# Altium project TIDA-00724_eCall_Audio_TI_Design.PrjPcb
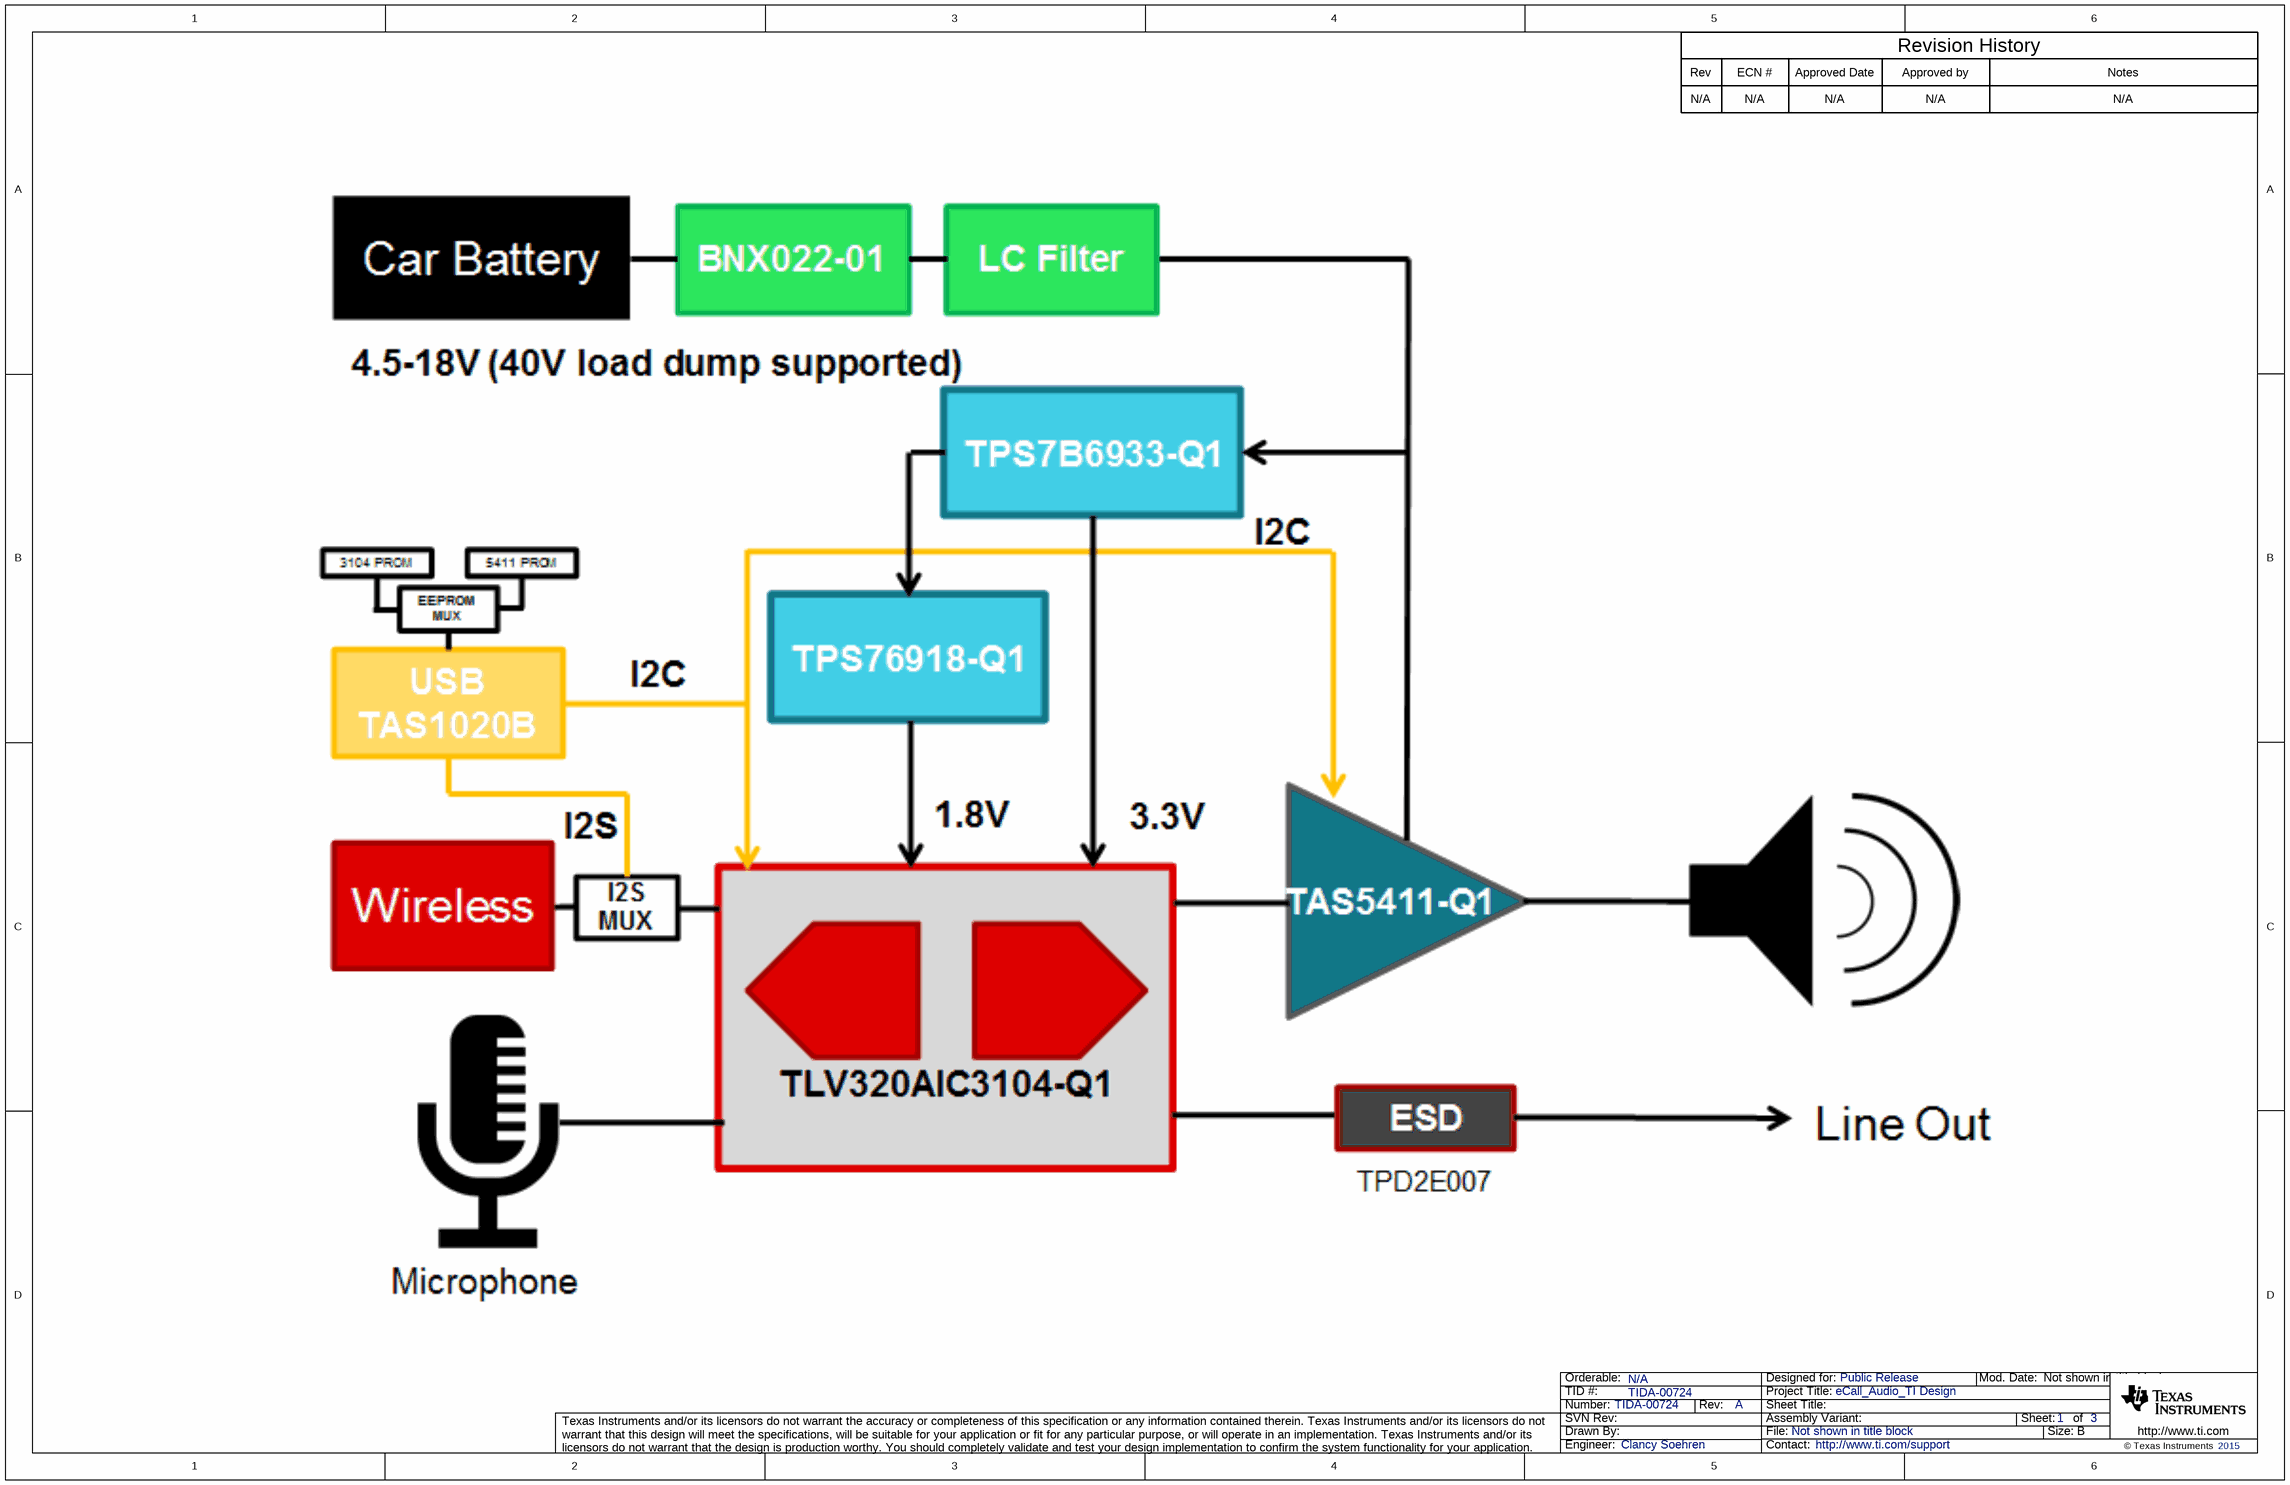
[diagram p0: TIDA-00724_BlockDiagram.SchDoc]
CopyrightYear: 2015; EVM_Orderable: N/A; PCB_Layout: Krypton Solutions; PCB_Rev: A; PRJ_Customer: Public Release; PRJ_Engineer: Clancy Soehren; PRJ_Number: TIDA-00724; PRJ_Title: eCall_Audio_TI Design; SCH_Rev: A; TechSupport: http://www.ti.com/support; TID: TIDA-00724
5 sheets, 148 parts. Net scope: global (net labels, ports and power ports of the same name join across sheets).
Board file: TIDA-00724_BRD.PcbDoc
Sheets:
  TIDA-00724_BlockDiagram.SchDoc
  TIDA-00724_Hardware.SchDoc
  TIDA-00724_Power.SchDoc
  TIDA-00724_TAS1020.SchDoc
  TIDA-00724_Audio.SchDoc

## Sheet TIDA-00724_BlockDiagram.SchDoc
size 431 x 279 mm; Date: Not shown in title block; ApprovedBy: Not shown in title block; CheckedBy: Not shown in title block; Author: Not shown in title block; CompanyName: Not shown in title block; Engineer: Not shown in title block; Organization: Not shown in title block; Address1: Not shown in title block; Address2: Not shown in title block; Address3: Not shown in title block; Address4: Not shown in title block; DocumentNumber: 1; Revision: Use project parameter SCH_Rev; SheetNumber: 1; SheetTotal: 3; PageSetup: Record=PageOptions¦CenterHorizontal=True¦CenterVertical=True¦PrintScale=1.00¦XCorrection=1.00¦YCorrection=1.00¦PrintKind=0¦BorderSize=5000000¦LeftOffset=0¦BottomOffset=0¦Orientation=2¦PaperLength=1000¦PaperWidth=1000¦Scale=100¦PaperSource=15¦PrintQuality=600¦MediaType=1¦DitherType=10¦PaperKind=Letter¦PrintScaleMode=1

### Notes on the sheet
- Rev
- N/A
- ECN #
- Approved Date
- Approved by
- Revision History
- Notes

## Sheet TIDA-00724_Hardware.SchDoc
size 431 x 279 mm; Date: Not shown in title block; ApprovedBy: Not shown in title block; CheckedBy: Not shown in title block; Author: Not shown in title block; CompanyName: Not shown in title block; Engineer: Not shown in title block; Organization: Not shown in title block; Address1: Not shown in title block; Address2: Not shown in title block; Address3: Not shown in title block; Address4: Not shown in title block; DocumentNumber: 1; Revision: Use project parameter SCH_Rev; SheetNumber: 3; SheetTotal: 3; PageSetup: Record=PageOptions¦CenterHorizontal=True¦CenterVertical=True¦PrintScale=1.00¦XCorrection=1.00¦YCorrection=1.00¦PrintKind=0¦BorderSize=5000000¦LeftOffset=0¦BottomOffset=0¦Orientation=2¦PaperLength=1000¦PaperWidth=1000¦Scale=100¦PaperSource=15¦PrintQuality=600¦MediaType=1¦DitherType=10¦PaperKind=Letter¦PrintScaleMode=1
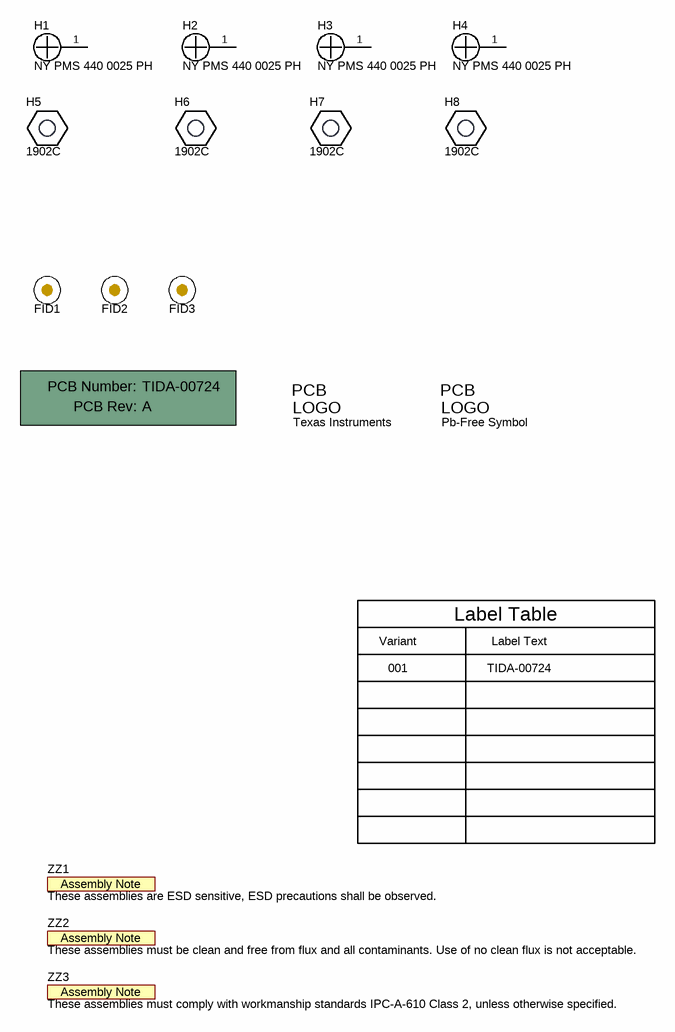
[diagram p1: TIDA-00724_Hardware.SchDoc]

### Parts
!PCB1  Printed Circuit Board  (value not drawn)  (mechanical)
FID1  Fiducial  [Fiducial10-20]  (value not drawn)
FID2  Fiducial  [Fiducial10-20]  (value not drawn)
FID3  Fiducial  [Fiducial10-20]  (value not drawn)
H1  NY PMS 440 0025 PH  [NY PMS 440 0025 PH]
H2  NY PMS 440 0025 PH  [NY PMS 440 0025 PH]
H3  NY PMS 440 0025 PH  [NY PMS 440 0025 PH]
H4  NY PMS 440 0025 PH  [NY PMS 440 0025 PH]
H5  1902C  [Keystone_1902C]
H6  1902C  [Keystone_1902C]
H7  1902C  [Keystone_1902C]
H8  1902C  [Keystone_1902C]
Logo1  Texas Instruments  [TI_Stacked_Overlay_Small]  (no BOM)
Logo2  Pb-Free Symbol  [Pb-Free_Overlay_Small]  (no BOM)
ZZ1  These assemblies are ESD sensitive, ESD precautions shall be observed.  [AssemblyNote]  (no BOM)
ZZ2  These assemblies must be clean and free from flux and all contaminants. Use of no clean flux is not acceptable.  [AssemblyNote]  (no BOM)
ZZ3  These assemblies must comply with workmanship standards IPC-A-610 Class 2, unless otherwise specified.  [AssemblyNote]  (no BOM)

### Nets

Not connected (* = marked no-connect by the designer): H1 1; H2 1; H3 1; H4 1

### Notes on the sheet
- Variant
- Label Table
- Label Text
- 001
- TIDA-00724

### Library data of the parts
!PCB1 = PCB: Manufacturer: Any; PartNumber: TIDA-00724; SymbolCreator: a0412235
FID1-FID3 = Fiducial: Fiducial mark.  There is nothing to buy or mount.; SymbolCreator: codlsc
H1-H4 = NY PMS 440 0025 PH: Machine Screw, Round, #4-40 x 1/4, Nylon, Philips panhead; Manufacturer: B&F Fastener Supply; CompType: Hardware; SymbolCreator: codlsc; U/M: EA
H5-H8 = 1902C: Standoff, Hex, 0.5"L #4-40 Nylon; Manufacturer: Keystone; CompType: Hardware
Logo1 = TI_Logo: Texas Instrument Corporate Signature; SymbolCreator: codlsc
Logo2 = Pb-Free: SymbolCreator: a0412235
ZZ1-ZZ3 = AssemblyNote: SymbolCreator: codlsc

## Sheet TIDA-00724_Power.SchDoc
size 431 x 279 mm; Date: Not shown in title block; ApprovedBy: Not shown in title block; CheckedBy: Not shown in title block; Author: Not shown in title block; CompanyName: Not shown in title block; Engineer: Not shown in title block; Organization: Not shown in title block; Address1: Not shown in title block; Address2: Not shown in title block; Address3: Not shown in title block; Address4: Not shown in title block; DocumentNumber: 1; Revision: Use project parameter SCH_Rev; SheetNumber: 2; SheetTotal: 3; PageSetup: Record=PageOptions¦CenterHorizontal=True¦CenterVertical=True¦PrintScale=0.62¦XCorrection=1.00¦YCorrection=1.00¦PrintKind=0¦BorderSize=5000000¦LeftOffset=0¦BottomOffset=0¦Orientation=2¦PaperLength=1000¦PaperWidth=1000¦Scale=100¦PaperSource=15¦PrintQuality=600¦MediaType=1¦DitherType=10¦PrintScaleMode=1¦PaperKind=Letter
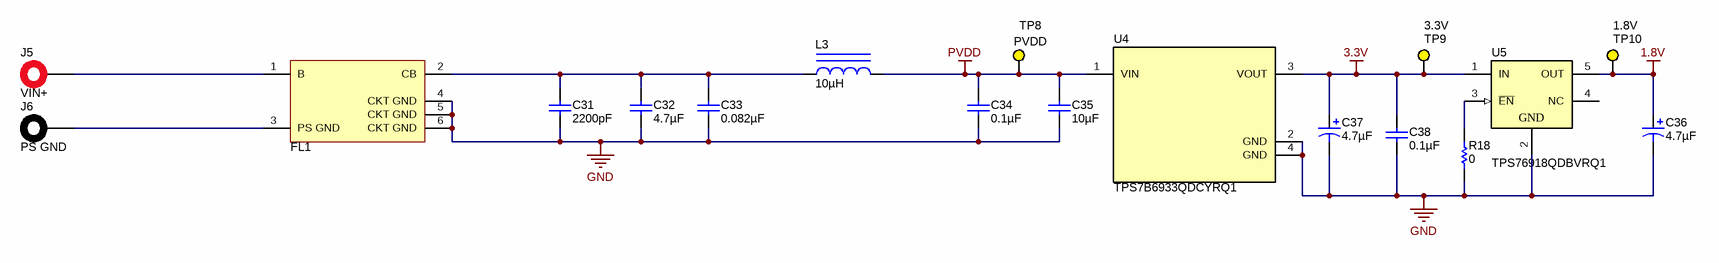
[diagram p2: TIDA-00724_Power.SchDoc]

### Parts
C31  ValueDisplayed: 2200pF  [0603]  (hidden comment: GRM188R71H222KA01D)
C32  ValueDisplayed: 4.7µF  [1206]  (hidden comment: GRM31CR71E475KA88L)
C33  ValueDisplayed: 0.082µF  [0603]  (hidden comment: GRM188R71E823KA01D)
C34  ValueDisplayed: 0.1µF  [0603]  (hidden comment: GRM188R71E104KA01D)
C35  ValueDisplayed: 10µF  [1206_190]  (hidden comment: GRM31CR61H106KA12L)
C36  ValueDisplayed: 4.7µF  [6032-28]  (hidden comment: TPSC475K035R0600)
C37  ValueDisplayed: 4.7µF  [6032-28]  (hidden comment: TPSC475K035R0600)
C38  ValueDisplayed: 0.1µF  [0603]  (hidden comment: GRM188R71E104KA01D)
FL1  BNX022-01L  [FIL_BNX02X]  (value not drawn)
J5  VIN+  [Tenma_SPC15363]
J6  PS GND  [Tenma_SPC15354]
L3  ValueDisplayed: 10µH  [SER1360]  (hidden comment: SER1360-103KLB)
R18  ValueDisplayed: 0  [0402]  (hidden comment: ERJ-2GE0R00X)
TP8  PVDD  [Keystone5009]
TP9  3.3V  [Keystone5009]
TP10  1.8V  [Keystone5009]
U4  TPS7B6933QDCYRQ1  [DCY0004A_N]
U5  TPS76918QDBVRQ1  [DBV0005A_N]

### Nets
1.8V: C36.1(+) TP10.1 U5.5(OUT)
3.3V: C37.1(+) C38.1 TP9.1 U4.3(VOUT) U5.1(IN)
GND: C31.2 C32.2 C33.2 C34.2 C35.2 C36.2(-) C37.2(-) C38.2 FL1.4(CKT_GND) FL1.5(CKT_GND) FL1.6(CKT_GND) R18.1 U4.2(GND) U4.4(GND) U5.2(GND)
PVDD: C34.1 C35.1 L3.2 TP8.1 U4.1(VIN)
NetC31_1: C31.1 C32.1 C33.1 FL1.2(CB) L3.1
NetFL1_1: FL1.1(B) J5.1
NetFL1_3: FL1.3(PS_GND) J6.1
NetR18_2: R18.2 U5.3(~{EN})

Not connected (* = marked no-connect by the designer): U5 4(NC)

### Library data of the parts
C31 = GRM188R71H222KA01D: CAP, CERM, 2200 pF, 50 V, +/- 10%, X7R, 0603; Manufacturer: MuRata; Polarized: N; CompType: Capacitor; Value: 2200pF; U/M: EA; Cap_F: 0.0000000022; Tolerance_%: 10; Value1: Unknown; VDC_V: 50; Value2: 50V; TaMin_C: -55; TaMax_C: 125
C32 = GRM31CR71E475KA88L: CAP, CERM, 4.7 µF, 25 V, +/- 10%, X7R, 1206; Manufacturer: MuRata; Polarized: N; CompType: Capacitor; Value: 4.7uF; U/M: EA; Cap_F: 0.0000047; Tolerance_%: 10; Value1: Unknown; VDC_V: 25; Value2: 25V; TaMin_C: -55; TaMax_C: 125
C33 = GRM188R71E823KA01D: CAP, CERM, 0.082 µF, 25 V, +/- 10%, X7R, 0603; Manufacturer: MuRata; Polarized: N; CompType: Capacitor; Value: 0.082uF; U/M: EA; Cap_F: 0.000000082; Tolerance_%: 10; Value1: Unknown; VDC_V: 25; Value2: 25V; TaMin_C: -55; TaMax_C: 125
C34 C38 = GRM188R71E104KA01D: CAP, CERM, 0.1 µF, 25 V, +/- 10%, X7R, 0603; Manufacturer: MuRata; Polarized: N; CompType: Capacitor; Value: 0.1uF; U/M: EA; Cap_F: 0.0000001; Tolerance_%: 10; Value1: Unknown; VDC_V: 25; Value2: 25V; TaMin_C: -55; TaMax_C: 125
C35 = GRM31CR61H106KA12L: CAP, CERM, 10 µF, 50 V, +/- 10%, X5R, 1206_190; Manufacturer: MuRata; Polarized: N; CompType: Capacitor; Value: 10uF; U/M: EA; Cap_F: 0.00001; Tolerance_%: 10; Value1: Unknown; VDC_V: 50; Value2: 50V; TaMin_C: -55; TaMax_C: 85; Cap_Case: 1206
C36 C37 = TPSC475K035R0600: CAP, TA, 4.7 µF, 35 V, +/- 10%, 0.6 ohm, SMD; Manufacturer: AVX; Polarized: Y; CompType: Capacitor; Value: 4.7uF; U/M: EA; Cap_F: 0.0000047; Tolerance_%: 10; Value1: 0.6 ohm; VDC_V: 35; Value2: 35V; ESR_ohm: 0.6; IRMS_A: 0.385; TaMin_C: -55; TaMax_C: 125; Cap_Case: C
FL1 = BNX022-01L: Filter, EMI, 10A 50V 1MHZ-1GHZ SMD; Manufacturer: MuRata; SymbolCreator: a0411947
J5 = SPC15363: BANANA JACK, SOLDER LUG, RED, TH; Manufacturer: Tenma; SymbolCreator: a0412235; U/M: EA
J6 = SPC15354: BANANA JACK, SOLDER LUG, BLACK, TH; Manufacturer: Tenma; SymbolCreator: a0412235; U/M: EA
L3 = SER1360-103KLB: Inductor, Shielded E Core, Ferrite, 10 µH, 7.2 A, 0.01 ohm, SMD; Manufacturer: Coilcraft; Value: 10uH; Ind_H: 10.0E-6; Imax_A: 7.2; Irms: 7.2A @ 40C rise; Isat: 7.5A @ 30% inductance drop; DCR_ohm: 0.01; Value2: 7.2A
R18 = ERJ-2GE0R00X: RES, 0, 5%, 0.063 W, 0402; Manufacturer: Panasonic; CompType: Resistor; Value: 0; Value_Code: 0000; Tolerance_%: 5; Power_W: 0.063; Value2: 0.063W; VDC_V: 50; TempCo: 600 ppm/C; EIA_Code: E24; U/M: EA
TP8-TP10 = 5009: Test Point, Compact, Yellow, TH; Manufacturer: Keystone; CompType: Test Point Loop; U/M: EA
U4 = TPS7B6933QDCYRQ1: High Voltage Ultra Low Iq - Low Drop Out Regulator, DCY0004A; Manufacturer: Texas Instruments; SymbolCreator: Altium; CompType: IC; U/M: EA
U5 = TPS76918QDBVRQ1: Single Output Automotive LDO, 100 mA, Fixed 1.8 V Output, 2.7 to 10 V Input, 5-pin SOT-23 (DBV), -40 to 125 degC, Green (RoHS & no Sb/Br); Manufacturer: Texas Instruments; Alternate PartNumber: Equivalent; Accuracy(%): 3; Fixed Output Options(V): 1.8; Iout(Max)(A): 0.1; Iq(Typ)(mA): 0.02; SubFamily: Single Channel LDO; Vdo(Typ)(mV): 71; Vin(Max)(V): 10; Vin(Min)(V): 2.7

## Sheet TIDA-00724_TAS1020.SchDoc
size 431 x 279 mm; Date: Not shown in title block; ApprovedBy: Not shown in title block; CheckedBy: Not shown in title block; Author: Not shown in title block; CompanyName: Not shown in title block; Engineer: Not shown in title block; Organization: Not shown in title block; Address1: Not shown in title block; Address2: Not shown in title block; Address3: Not shown in title block; Address4: Not shown in title block; DocumentNumber: 1; Revision: Use project parameter SCH_Rev; SheetNumber: 2; SheetTotal: 3; PageSetup: Record=PageOptions¦CenterHorizontal=True¦CenterVertical=True¦PrintScale=0.96¦XCorrection=1.00¦YCorrection=1.00¦PrintKind=0¦BorderSize=5000000¦LeftOffset=0¦BottomOffset=0¦Orientation=2¦PaperLength=1000¦PaperWidth=1000¦Scale=100¦PaperSource=15¦PrintQuality=600¦MediaType=1¦DitherType=10¦PrintScaleMode=1¦PaperKind=11x17¦PaperIndex=17
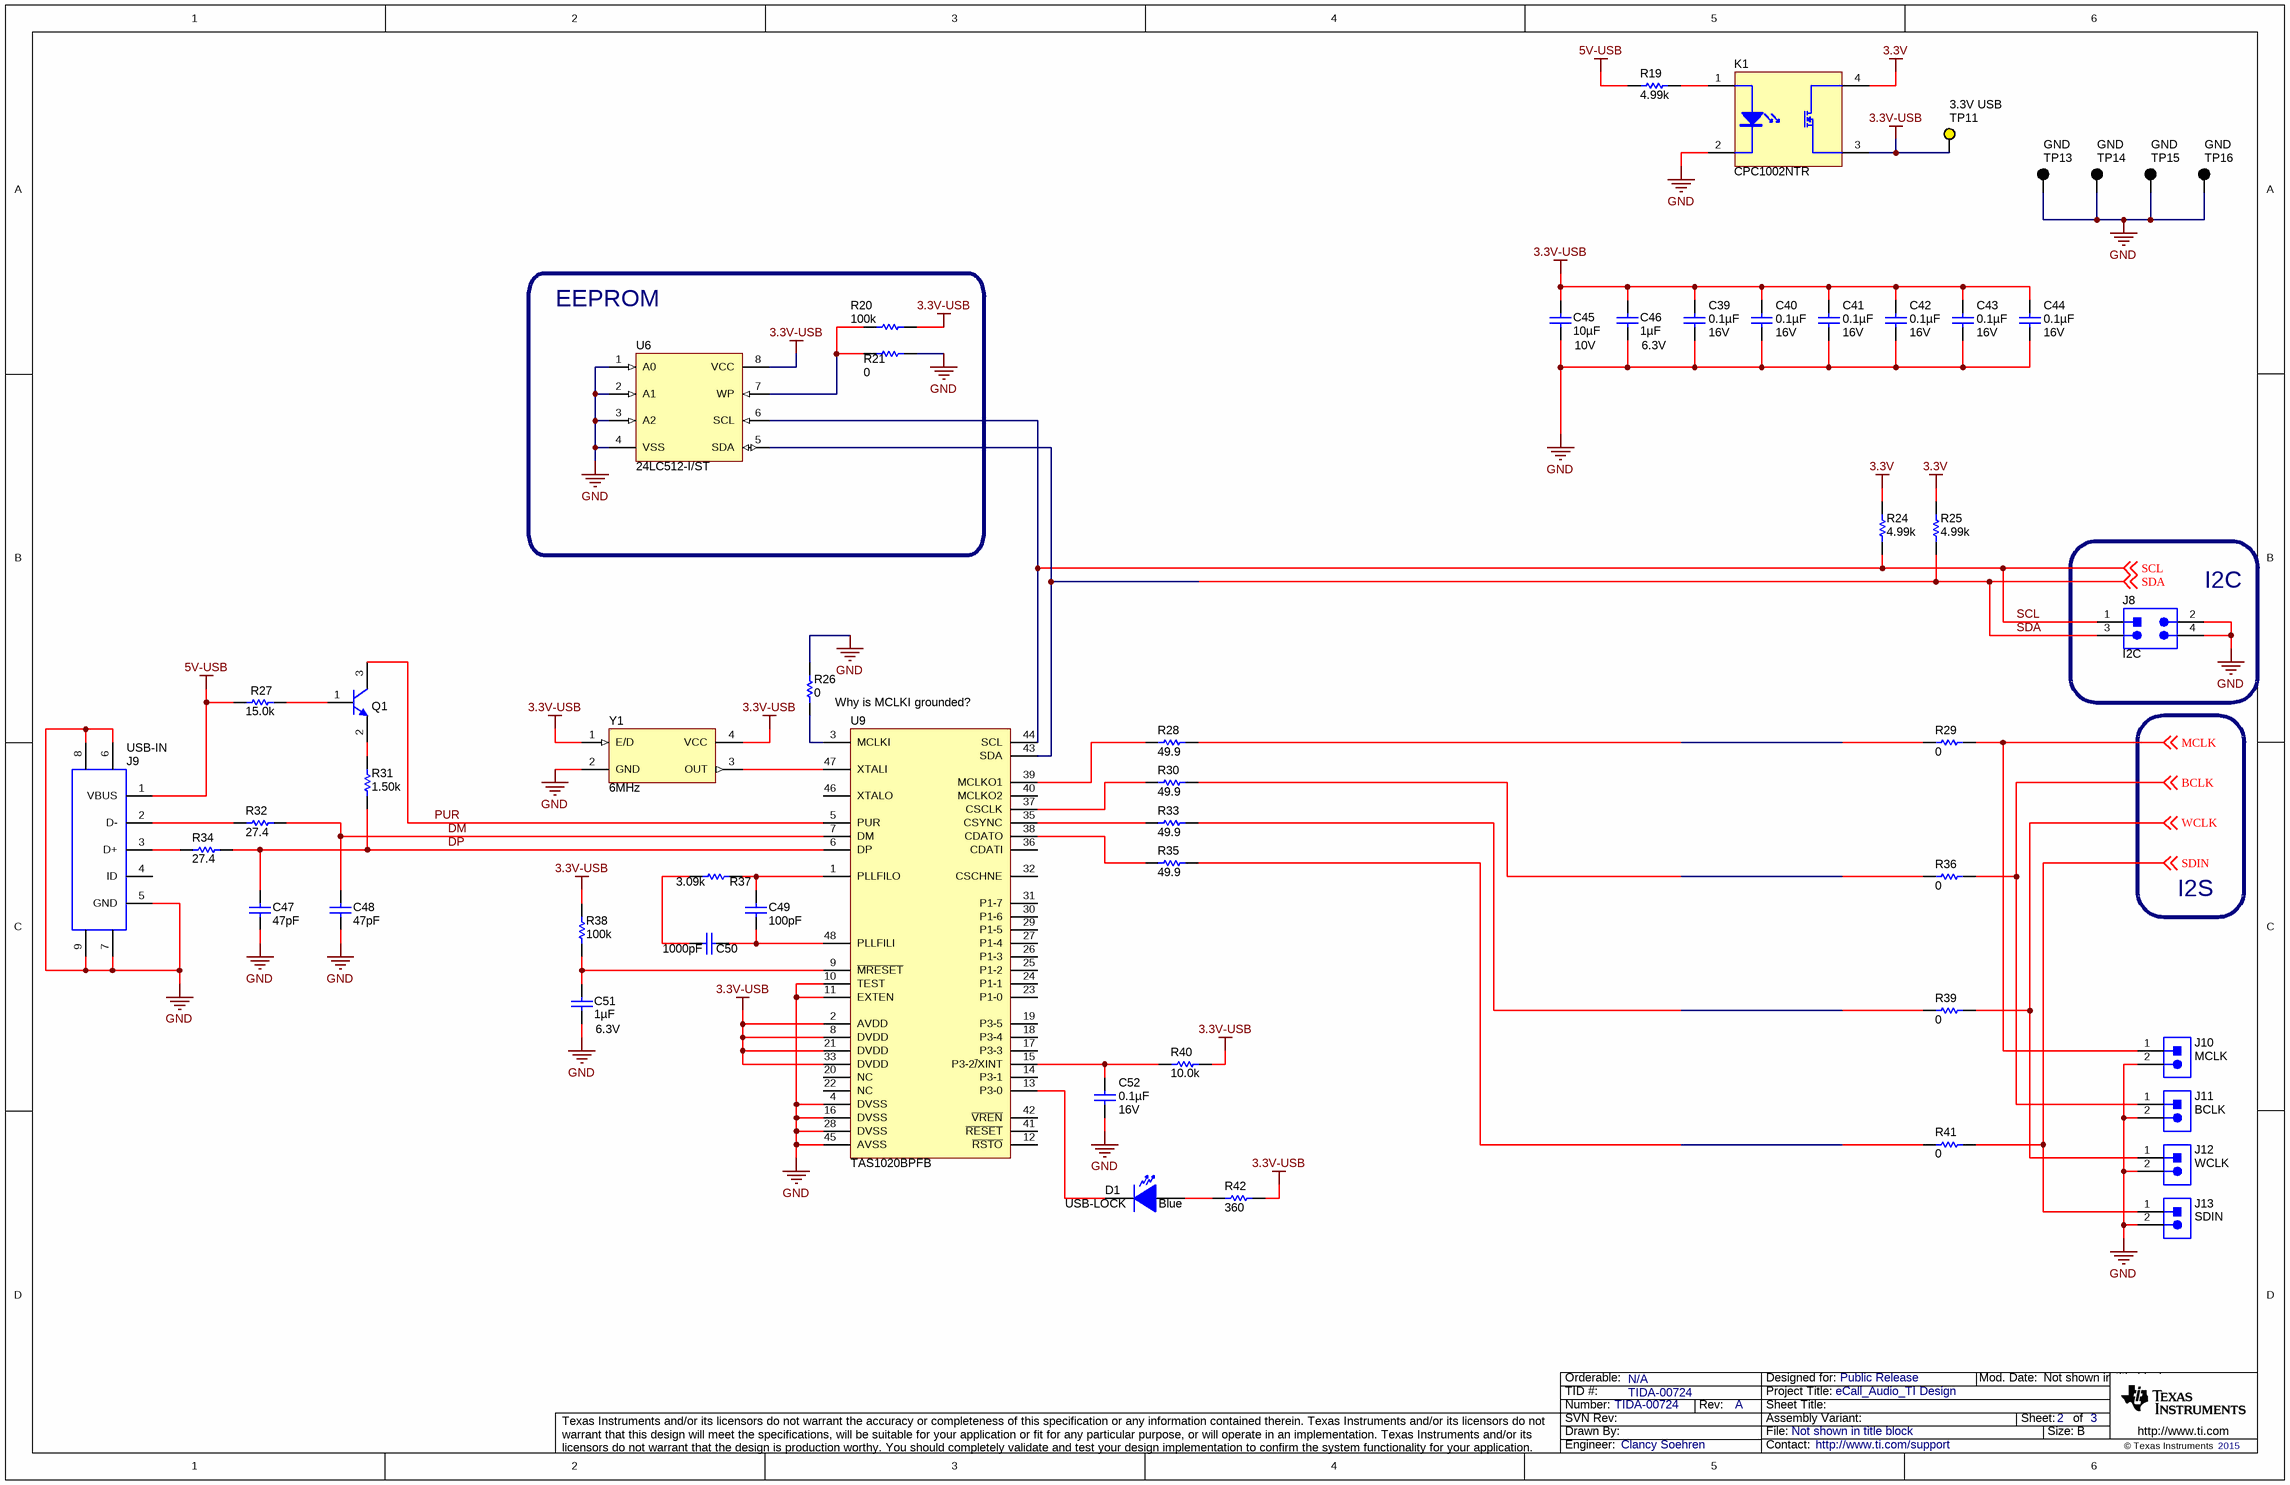
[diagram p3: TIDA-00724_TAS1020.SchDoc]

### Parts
C39  ValueDisplayed: 0.1µF  Value2: 16V  [0402L]  (hidden comment: GRM155R71C104KA88D)
C40  ValueDisplayed: 0.1µF  Value2: 16V  [0402L]  (hidden comment: GRM155R71C104KA88D)
C41  ValueDisplayed: 0.1µF  Value2: 16V  [0402L]  (hidden comment: GRM155R71C104KA88D)
C42  ValueDisplayed: 0.1µF  Value2: 16V  [0402L]  (hidden comment: GRM155R71C104KA88D)
C43  ValueDisplayed: 0.1µF  Value2: 16V  [0402L]  (hidden comment: GRM155R71C104KA88D)
C44  ValueDisplayed: 0.1µF  Value2: 16V  [0402L]  (hidden comment: GRM155R71C104KA88D)
C45  ValueDisplayed: 10µF  Value2: 10V  [0603L]  (hidden comment: C1608X5R1A106M)
C46  ValueDisplayed: 1µF  Value2: 6.3V  [0402L]  (hidden comment: C1005X5R0J105M)
C47  ValueDisplayed: 47pF  [0402L]  (hidden comment: GRM1555C1E470JA01D)
C48  ValueDisplayed: 47pF  [0402L]  (hidden comment: GRM1555C1E470JA01D)
C49  ValueDisplayed: 100pF  [0402L]  (hidden comment: GRM1555C1H101JA01D)
C50  ValueDisplayed: 1000pF  [0402L]  (hidden comment: GRM1555C1H102JA01D)
C51  ValueDisplayed: 1µF  Value2: 6.3V  [0402L]  (hidden comment: C1005X5R0J105M)
C52  ValueDisplayed: 0.1µF  Value2: 16V  [0402L]  (hidden comment: GRM155R71C104KA88D)
D1  USB-LOCK  value Blue  [LED_SMLP12_BLUE]
J8  I2C  [Sullins_PEC02DAAN]
J9  USB-IN  [CONN_USB_DX4R205JJA]
J10  MCLK  [Sullins_PBC02SAAN]
J11  BCLK  [Sullins_PBC02SAAN]
J12  WCLK  [Sullins_PBC02SAAN]
J13  SDIN  [Sullins_PBC02SAAN]
K1  CPC1002NTR  [RELAY_CPC1002N]
Q1  MMBT2222A  [SOT-23]  (value not drawn)
R19  ValueDisplayed: 4.99k  [0603L]  (hidden comment: CRCW06034K99FKEA)
R20  value 100k  [0402L]  (hidden comment: CRCW0402100KFKED)
R21  ValueDisplayed: 0  [0603L]  (hidden comment: CRCW06030000Z0EA)
R24  value 4.99k  [0402L]  (hidden comment: CRCW04024K99FKED)
R25  value 4.99k  [0402L]  (hidden comment: CRCW04024K99FKED)
R26  ValueDisplayed: 0  [0603L]  (hidden comment: CRCW06030000Z0EA)
R27  value 15.0k  [0402L]  (hidden comment: CRCW040215K0FKED)
R28  value 49.9  [0402L]  (hidden comment: CRCW040249R9FKED)
R29  ValueDisplayed: 0  [0402L]  (hidden comment: CRCW04020000Z0ED)
R30  value 49.9  [0402L]  (hidden comment: CRCW040249R9FKED)
R31  value 1.50k  [0402L]  (hidden comment: CRCW04021K50FKED)
R32  value 27.4  [0402L]  (hidden comment: CRCW040227R4FKED)
R33  value 49.9  [0402L]  (hidden comment: CRCW040249R9FKED)
R34  value 27.4  [0402L]  (hidden comment: CRCW040227R4FKED)
R35  value 49.9  [0402L]  (hidden comment: CRCW040249R9FKED)
R36  ValueDisplayed: 0  [0402L]  (hidden comment: CRCW04020000Z0ED)
R37  value 3.09k  [0402L]  (hidden comment: CRCW04023K09FKED)
R38  value 100k  [0402L]  (hidden comment: CRCW0402100KFKED)
R39  ValueDisplayed: 0  [0402L]  (hidden comment: CRCW04020000Z0ED)
R40  ValueDisplayed: 10.0k  [0402L]  (hidden comment: CRCW040210K0FKED)
R41  ValueDisplayed: 0  [0402L]  (hidden comment: CRCW04020000Z0ED)
R42  value 360  [0402L]  (hidden comment: CRCW0402360RJNED)
TP11  3.3V USB  [Keystone5009]
TP13  GND  [Keystone5006]
TP14  GND  [Keystone5006]
TP15  GND  [Keystone5006]
TP16  GND  [Keystone5006]
U6  24LC512-I/ST  [TSSOP-8]
U9  TAS1020BPFB  [PFB0048A_N]
Y1  Frequency: 6MHz  [OSC_CTS_625]  (hidden comment: 625L3I006M00000)

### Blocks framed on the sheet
EEPROM: R20 R21 U6
I2C: J8

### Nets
3.3V: K1.4(DC+) R24.2 R25.2
3.3V-USB: C39.1 C40.1 C41.1 C42.1 C43.1 C44.1 C45.1 C46.2 K1.3(DC-) R20.2 R38.2 R40.2 R42.1 TP11.1 U6.8(VCC) U9.2(AVDD) U9.8(DVDD) U9.21(DVDD) U9.33(DVDD) Y1.1(E/D) Y1.4(VCC)
5V-USB: J9.1(VBUS) R19.2 R27.1
GND: C39.2 C40.2 C41.2 C42.2 C43.2 C44.2 C45.2 C46.1 C47.1 C48.1 C51.1 C52.2 J8.2 J8.4 J9.5(GND) J9.6 J9.7 J9.8 J9.9 J10.2 J11.2 J12.2 J13.2 K1.2(C) R21.2 R26.2 TP13.1 TP14.1 TP15.1 TP16.1 U6.1(A0) U6.2(A1) U6.3(A2) U6.4(VSS) U9.4(DVSS) U9.10(TEST) U9.11(EXTEN) U9.16(DVSS) U9.28(DVSS) U9.45(AVSS) Y1.2(GND)
BCLK: J11.1 R36.1 ; off-sheet BCLK
DM: C48.2 R32.2 U9.7(DM)
DP: C47.2 R31.2 R34.2 U9.6(DP)
MCLK: J10.1 R29.1 ; off-sheet MCLK
PUR: Q1.3(C) U9.5(PUR)
SCL: J8.1 R24.1 U6.6(SCL) U9.44(SCL) ; off-sheet SCL
SDA: J8.3 R25.1 U6.5(SDA) U9.43(SDA) ; off-sheet SDA
SDIN: J13.1 R41.1 ; off-sheet SDIN
WCLK: J12.1 R39.1 ; off-sheet WCLK
NetC49_1: C49.1 R37.2 U9.1(PLLFILO)
NetC49_2: C49.2 C50.1 U9.48(PLLFILI)
NetC50_2: C50.2 R37.1
NetC51_2: C51.2 R38.1 U9.9(~{MRESET})
NetC52_1: C52.1 R40.1 U9.15(P3-2~{/}XINT)
NetD1_1: D1.1(A) R42.2
NetD1_2: D1.2(K) U9.13(P3-0)
NetJ9_2: J9.2(D-) R32.1
NetJ9_3: J9.3(D+) R34.1
NetK1_1: K1.1(A) R19.1
NetQ1_1: Q1.1(B) R27.2
NetQ1_2: Q1.2(E) R31.1
NetR20_1: R20.1 R21.1 U6.7(WP)
NetR26_1: R26.1 U9.3(MCLKI)
NetR28_1: R28.1 U9.39(MCLKO1)
NetR28_2: R28.2 R29.2
NetR30_1: R30.1 U9.37(CSCLK)
NetR30_2: R30.2 R36.2
NetR33_1: R33.1 U9.35(CSYNC)
NetR33_2: R33.2 R39.2
NetR35_1: R35.1 U9.38(CDATO)
NetR35_2: R35.2 R41.2
NetU9_47: U9.47(XTALI) Y1.3(OUT)

Not connected (* = marked no-connect by the designer): J9 4(ID); U9 12(~{RSTO}) 14(P3-1) 17(P3-3) 18(P3-4) 19(P3-5) 20(NC) 22(NC) 23(P1-0) 24(P1-1) 25(P1-2) 26(P1-3) 27(P1-4) 29(P1-5) 30(P1-6) 31(P1-7) 32(CSCHNE) 36(CDATI) 40(MCLKO2) 41(~{RESET}) 42(~{VREN}) 46(XTALO)

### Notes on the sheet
- Why is MCLKI grounded?
- I2S

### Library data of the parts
C39-C44 C52 = GRM155R71C104KA88D: CAP, CERM, 0.1uF, 16V, +/-10%, X7R, 0402; Manufacturer: MuRata; Polarized: N; CompType: Capacitor; U/M: EA; Cap_F: 0.0000001; Tolerance_%: 10; Value1: Unknown; VDC_V: 16; TaMin_C: -55; TaMax_C: 125; Cap_Case: 0402
C45 = C1608X5R1A106M: CAP, CERM, 10uF, 10V, +/-20%, X5R, 0603; Manufacturer: TDK; Polarized: N; CompType: Capacitor; U/M: EA; Cap_F: 0.00001; Tolerance_%: 20; ESR_Ohm: 0.0078; Value1: 0.0078 ohm; VDC_V: 10; IRMS_A: 1.85; TaMin_C: -55; TaMax_C: 85; Cap_Case: 0603
C46 C51 = C1005X5R0J105M: CAP, CERM, 1uF, 6.3V, +/-20%, X5R, 0402; Manufacturer: TDK; Polarized: N; CompType: Capacitor; U/M: EA; Cap_F: 0.000001; Tolerance_%: 20; ESR_Ohm: 0.0079; Value1: 0.0079 ohm; VDC_V: 6.3; TaMin_C: -55; TaMax_C: 85; Cap_Case: 0402
C47 C48 = GRM1555C1E470JA01D: CAP, CERM, 47pF, 25V, +/-5%, C0G/NP0, 0402; Manufacturer: MuRata; Polarized: N; CompType: Capacitor; U/M: EA; Cap_F: 0.000000000047; Tolerance_%: 5; Value1: Unknown; VDC_V: 25; TaMin_C: -55; TaMax_C: 125; Cap_Case: 0402
C49 = GRM1555C1H101JA01D: CAP, CERM, 100pF, 50V, +/-5%, C0G/NP0, 0402; Manufacturer: MuRata; Polarized: N; CompType: Capacitor; U/M: EA; Cap_F: 0.0000000001; Tolerance_%: 5; Value1: Unknown; VDC_V: 50; TaMin_C: -55; TaMax_C: 125; Cap_Case: 0402
C50 = GRM1555C1H102JA01D: CAP, CERM, 1000pF, 50V, +/-5%, C0G/NP0, 0402; Manufacturer: MuRata; Polarized: N; CompType: Capacitor; U/M: EA; Cap_F: 0.000000001; Tolerance_%: 5; Value1: Unknown; VDC_V: 50; TaMin_C: -55; TaMax_C: 125; Cap_Case: 0402
D1 = SMLP12BC7TT86: LED, Blue, SMD; Manufacturer: Rohm; Type: InGaN; Vf_V: 2.9; Value2: 2.9V; Io_A: 0.005; Tjmax_C: 85; Value1: W; U/M: EA
J8 = PEC02DAAN: Header, 100mil, 2x2, Tin, TH; Manufacturer: Sullins Connector Solutions; SymbolCreator: a0412235; U/M: EA
J9 = DX4R205JJAR1800: Connector, Receptacle, Micro-USB Type AB, R/A, Bottom Mount SMT; Manufacturer: JAE Electronics; SymbolCreator: a0799628; U/M: EA
J10-J13 = PBC02SAAN: Header, 100mil, 2x1, Gold, TH; Manufacturer: Sullins Connector Solutions; SymbolCreator: a0412235; U/M: EA
K1 = CPC1002NTR: Relay, SPST-NO (1 Form A), 0.7 A, , SMD; Manufacturer: IXYS; SymbolCreator: Altium; Contact Rating: 0.7 A; Time Operate (s): 0.005; Time Release (s): 0.002
Q1 = MMBT2222A, Fairchild Semiconductor: Transistor, NPN, 40V, 0.15A, SOT-23; CompType: BJT; PNP: 0; NPN: 1; Vceo_V: 40; Vcesat1_V: 0.3; Value: 0.3V; IcRated_A: 0.15; HfeMax: 300; TaMin_C: -55; TaMax_C: 150; U/M: EA
R19 = CRCW06034K99FKEA: RES, 4.99 k, 1%, 0.1 W, 0603; Manufacturer: Vishay-Dale; CompType: Resistor; Value: 4.99k; Res_ohm: 4990; Value_Code: 4k99; Tolerance_%: 1; Power_W: 0.1; Value2: 0.1W; VDC_V: 75; TempCo: 100 ppm/C; EIA_Code: E96; U/M: EA
R20 R38 = CRCW0402100KFKED: RES, 100k ohm, 1%, 0.063W, 0402; Manufacturer: Vishay-Dale; CompType: Resistor; Res_ohm: 100000; Tolerance_%: 1; Power_W: 0.063; VDC_V: 50; TempCo: 100 ppm/C; EIA_Code: E96; U/M: EA
R21 R26 = CRCW06030000Z0EA: RES, 0, 5%, 0.1 W, 0603; Manufacturer: Vishay-Dale; CompType: Resistor; Value: 0; Value_Code: 0000; Tolerance_%: 5; Power_W: 0.1; Value2: 0.1W; VDC_V: 75; TempCo: 200 ppm/C; EIA_Code: E24; U/M: EA
R24 R25 = CRCW04024K99FKED: RES, 4.99k ohm, 1%, 0.063W, 0402; Manufacturer: Vishay-Dale; CompType: Resistor; Res_ohm: 4990; Value_Code: 4k99; Tolerance_%: 1; Power_W: 0.063; VDC_V: 50; TempCo: 100 ppm/C; EIA_Code: E96; U/M: EA
R27 = CRCW040215K0FKED: RES, 15.0k ohm, 1%, 0.063W, 0402; Manufacturer: Vishay-Dale; CompType: Resistor; Res_ohm: 15000; Value_Code: 15k0; Tolerance_%: 1; Power_W: 0.063; VDC_V: 50; TempCo: 100 ppm/C; EIA_Code: E96; U/M: EA
R28 R30 R33 R35 = CRCW040249R9FKED: RES, 49.9 ohm, 1%, 0.063W, 0402; Manufacturer: Vishay-Dale; CompType: Resistor; Value_Code: 49R9; Tolerance_%: 1; Power_W: 0.063; VDC_V: 50; TempCo: 100 ppm/C; EIA_Code: E96; U/M: EA
R29 R36 R39 R41 = CRCW04020000Z0ED: RES, 0, 5%, 0.063 W, 0402; Manufacturer: Vishay-Dale; CompType: Resistor; Value: 0; Value_Code: 0000; Tolerance_%: 5; Power_W: 0.063; Value2: 0.063W; VDC_V: 50; TempCo: 200 ppm/C; EIA_Code: E24; U/M: EA
R31 = CRCW04021K50FKED: RES, 1.50k ohm, 1%, 0.063W, 0402; Manufacturer: Vishay-Dale; CompType: Resistor; Res_ohm: 1500; Value_Code: 1k50; Tolerance_%: 1; Power_W: 0.063; VDC_V: 50; TempCo: 100 ppm/C; EIA_Code: E96; U/M: EA
R32 R34 = CRCW040227R4FKED: RES, 27.4 ohm, 1%, 0.063W, 0402; Manufacturer: Vishay-Dale; CompType: Resistor; Value_Code: 27R4; Tolerance_%: 1; Power_W: 0.063; VDC_V: 50; TempCo: 100 ppm/C; EIA_Code: E96; U/M: EA
R37 = CRCW04023K09FKED: RES, 3.09k ohm, 1%, 0.063W, 0402; Manufacturer: Vishay-Dale; CompType: Resistor; Res_ohm: 3090; Value_Code: 3k09; Tolerance_%: 1; Power_W: 0.063; VDC_V: 50; TempCo: 100 ppm/C; EIA_Code: E96; U/M: EA
R40 = CRCW040210K0FKED: RES, 10.0 k, 1%, 0.063 W, 0402; Manufacturer: Vishay-Dale; CompType: Resistor; Value: 10.0k; Res_ohm: 10000; Value_Code: 10k0; Tolerance_%: 1; Power_W: 0.063; Value2: 0.063W; VDC_V: 50; TempCo: 100 ppm/C; EIA_Code: E96; U/M: EA
R42 = CRCW0402360RJNED: RES, 360 ohm, 5%, 0.063W, 0402; Manufacturer: Vishay-Dale; CompType: Resistor; Value_Code: 360R; Tolerance_%: 5; Power_W: 0.063; VDC_V: 50; TempCo: 200 ppm/C; EIA_Code: E24; U/M: EA
TP11 = 5009: as TP8 on sheet TIDA-00724_Power
TP13-TP16 = 5006: Test Point, Compact, Black, TH; Manufacturer: Keystone; CompType: Test Point Loop; U/M: EA
U6 = 24LC512-I/ST: EEPROM, 512KBIT, 400KHZ, 8TSSOP; Manufacturer: Microchip; SymbolCreator: a0411947
U9 = TAS1020BPFB: IC, USB Streaming Controller; Manufacturer: TI; Alternate Manufacturer: None; Area: 178084
Y1 = 625L3I006M00000: Oscillator, 6MHz, 3.3V, SMD; Manufacturer: CTS Electrocomponents; SymbolCreator: a0411947; U/M: EA; TaMin_C: -40; TaMax_C: 85; Frequency Stability: ±50ppm

## Sheet TIDA-00724_Audio.SchDoc
size 431 x 279 mm; Date: Not shown in title block; ApprovedBy: Not shown in title block; CheckedBy: Not shown in title block; Author: Not shown in title block; CompanyName: Not shown in title block; Engineer: Not shown in title block; Organization: Not shown in title block; Address1: Not shown in title block; Address2: Not shown in title block; Address3: Not shown in title block; Address4: Not shown in title block; DocumentNumber: 1; Revision: Use project parameter SCH_Rev; SheetNumber: 2; SheetTotal: 3; PageSetup: Record=PageOptions¦CenterHorizontal=True¦CenterVertical=True¦PrintScale=0.96¦XCorrection=1.00¦YCorrection=1.00¦PrintKind=0¦BorderSize=5000000¦LeftOffset=0¦BottomOffset=0¦Orientation=2¦PaperLength=1000¦PaperWidth=1000¦Scale=100¦PaperSource=15¦PrintQuality=600¦MediaType=1¦DitherType=10¦PrintScaleMode=1¦PaperKind=11x17¦PaperIndex=17
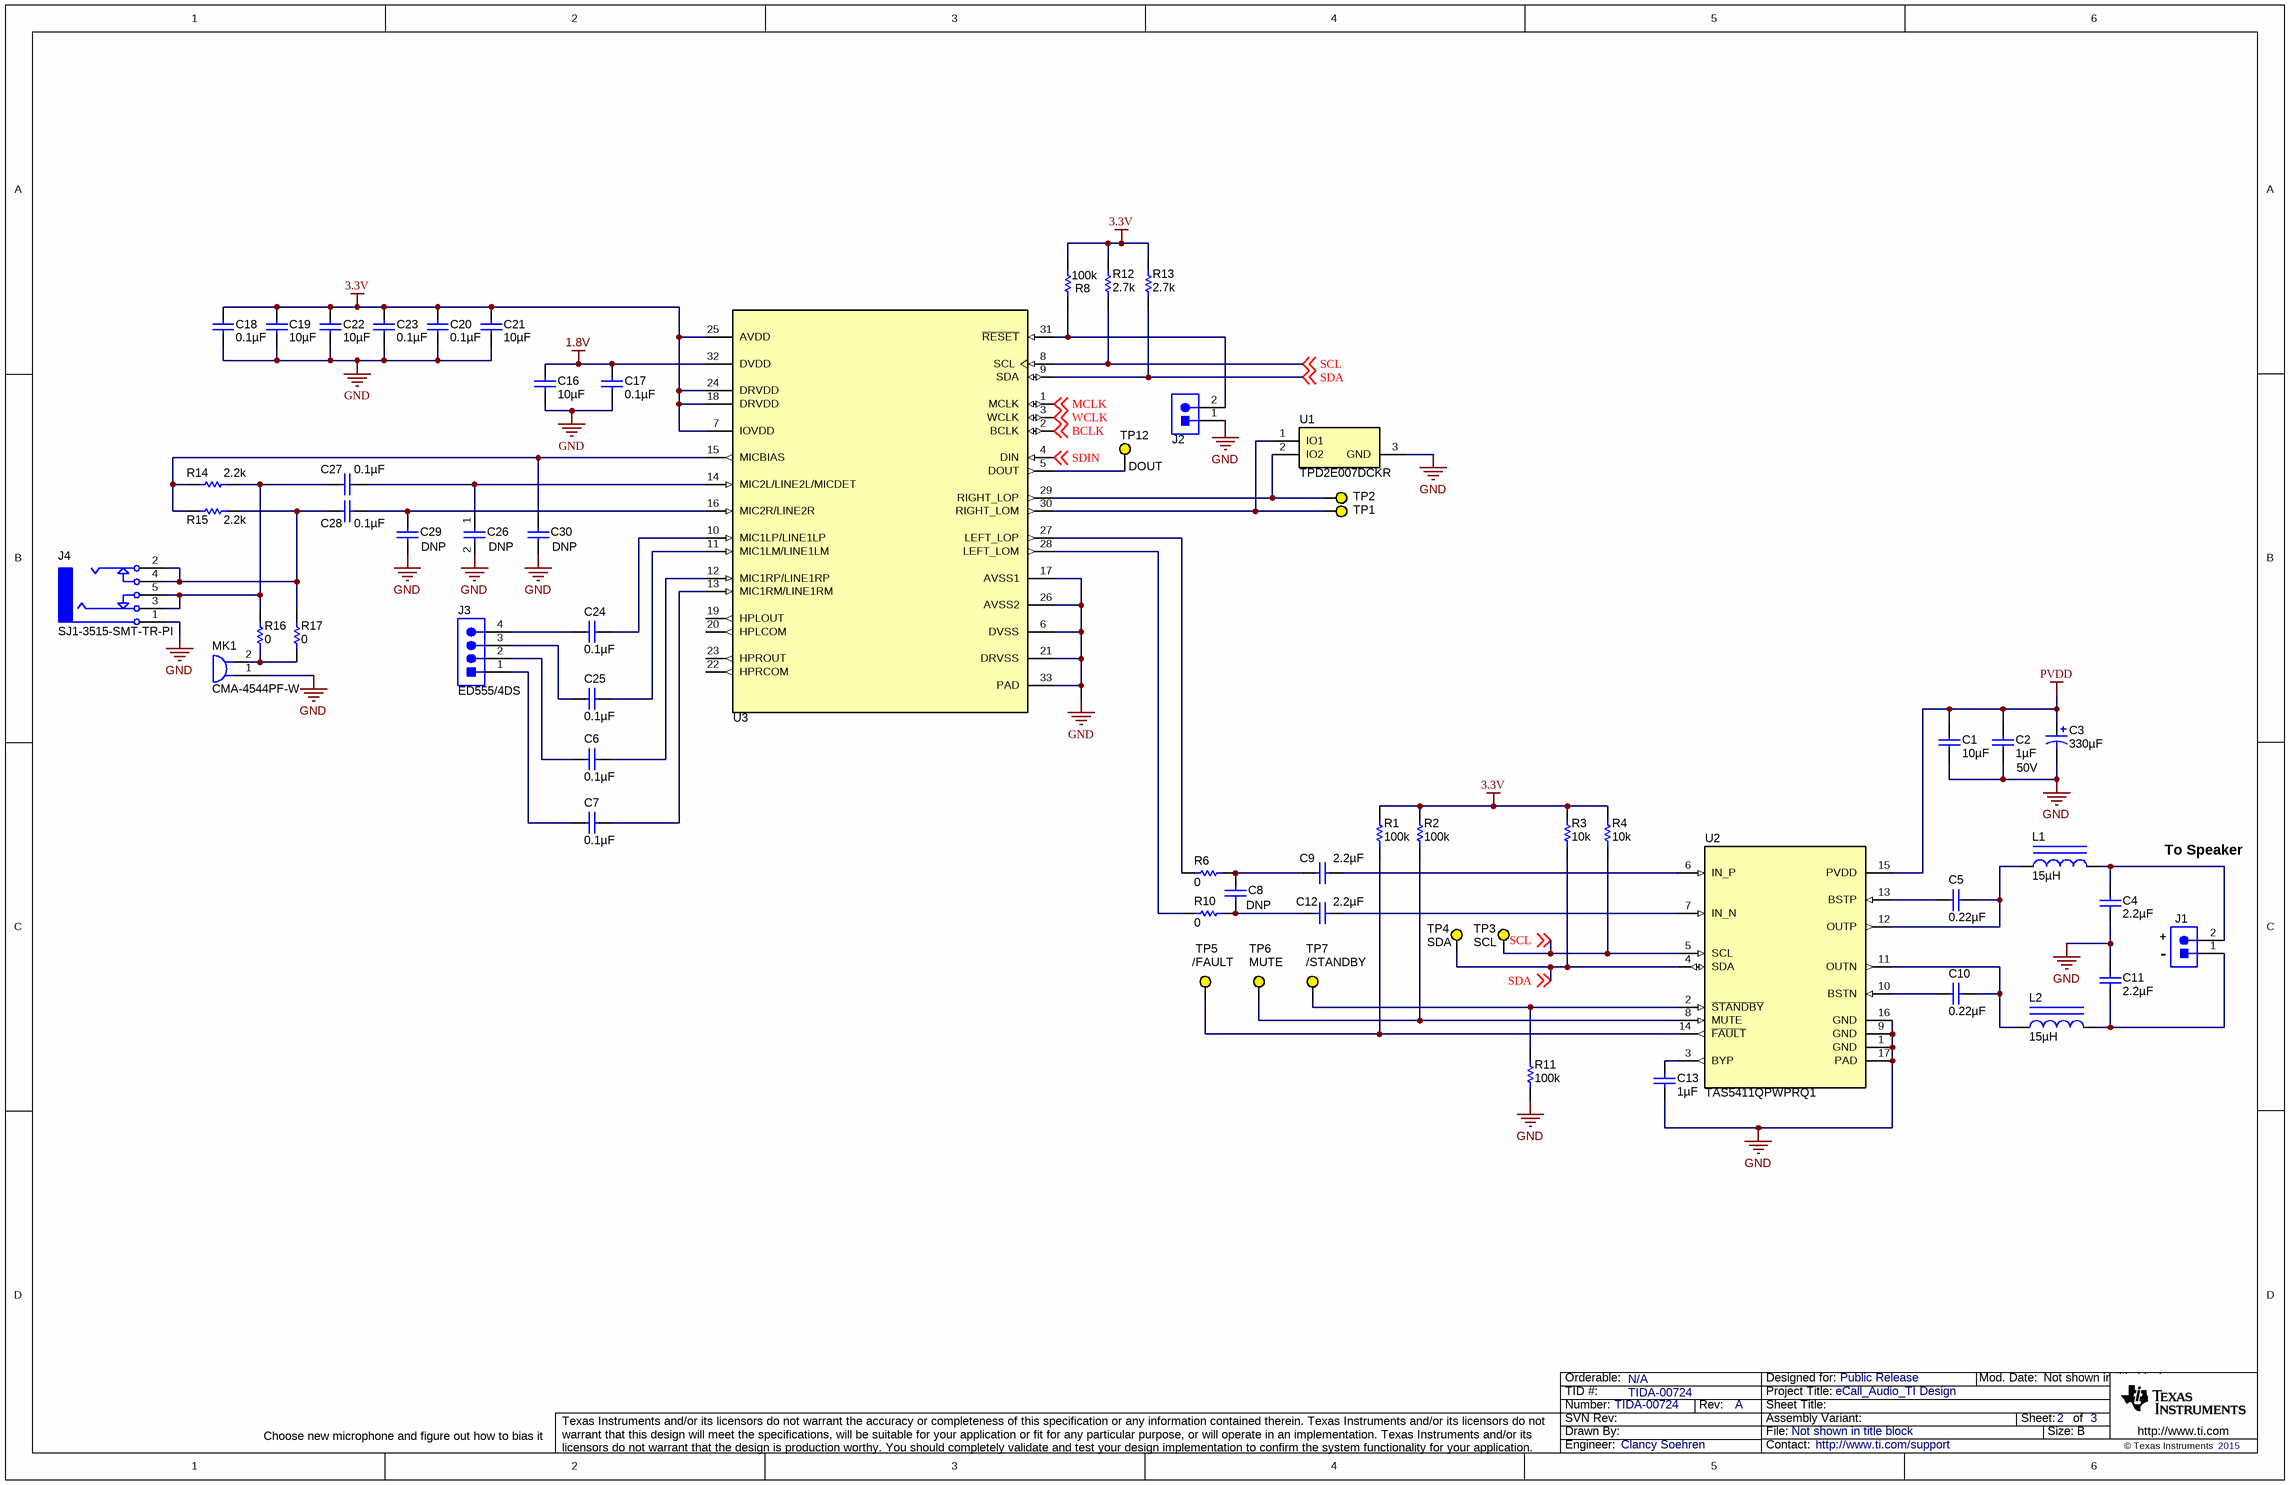
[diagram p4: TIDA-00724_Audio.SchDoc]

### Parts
C1  ValueDisplayed: 10µF  [0805_HV]  (hidden comment: C0805C106K9PAC)
C2  ValueDisplayed: 1µF  Value2: 50V  [0805_HV]  (hidden comment: GRM21BR71H105KA12L)
C3  ValueDisplayed: 330µF  [KZE_1000x2500]  (hidden comment: EKZE500ELL331MJ25S)
C4  ValueDisplayed: 2.2µF  [0805_HV]  (hidden comment: EMK212B7225KG-T)
C5  ValueDisplayed: 0.22µF  [0603]  (hidden comment: C1608X7R1H224K080AB)
C6  ValueDisplayed: 0.1µF  [0805_HV]  (hidden comment: C2012X7R2A104K)
C7  ValueDisplayed: 0.1µF  [0805_HV]  (hidden comment: C2012X7R2A104K)
C8  DNP  [0805_HV]
C9  ValueDisplayed: 2.2µF  [0805_HV]  (hidden comment: EMK212B7225KG-T)
C10  ValueDisplayed: 0.22µF  [0603]  (hidden comment: C1608X7R1H224K080AB)
C11  ValueDisplayed: 2.2µF  [0805_HV]  (hidden comment: EMK212B7225KG-T)
C12  ValueDisplayed: 2.2µF  [0805_HV]  (hidden comment: EMK212B7225KG-T)
C13  ValueDisplayed: 1µF  [0805_HV]  (hidden comment: GRM21BR71H105KA12L)
C16  ValueDisplayed: 10µF  [0805_HV]  (hidden comment: C0805C106K9PAC)
C17  ValueDisplayed: 0.1µF  [0603]  (hidden comment: C1608X7R1C104K)
C18  ValueDisplayed: 0.1µF  [0603]  (hidden comment: C1608X7R1C104K)
C19  ValueDisplayed: 10µF  [0805_HV]  (hidden comment: C0805C106K9PAC)
C20  ValueDisplayed: 0.1µF  [0603]  (hidden comment: C1608X7R1C104K)
C21  ValueDisplayed: 10µF  [0805_HV]  (hidden comment: C0805C106K9PAC)
C22  ValueDisplayed: 10µF  [0805_HV]  (hidden comment: C0805C106K9PAC)
C23  ValueDisplayed: 0.1µF  [0603]  (hidden comment: C1608X7R1C104K)
C24  ValueDisplayed: 0.1µF  [0805_HV]  (hidden comment: C2012X7R2A104K)
C25  ValueDisplayed: 0.1µF  [0805_HV]  (hidden comment: C2012X7R2A104K)
C26  DNP  [0603]
C27  ValueDisplayed: 0.1µF  [0805_HV]  (hidden comment: C2012X7R2A104K)
C28  ValueDisplayed: 0.1µF  [0805_HV]  (hidden comment: C2012X7R2A104K)
C29  DNP  [0603]
C30  DNP  [0603]
J1  ED555/2DS  [TERM_BLK_ED555-2DS]  (value not drawn)
J2  PBC02SAAN  [Sullins_PBC02SAAN]  (value not drawn)
J3  ED555/4DS  [TERM_BLK_ED555-4DS]
J4  SJ1-3515-SMT-TR-PI  [CUI_SJ1-351x-SMT-PI]
L1  ValueDisplayed: 15µH  [DFEG7030D]  (hidden comment: DFEG7030D-150M)
L2  ValueDisplayed: 15µH  [DFEG7030D]  (hidden comment: DFEG7030D-150M)
MK1  CMA-4544PF-W  [CUI_CMA-4544PF-W]
R1  value 100k  [0603]  (hidden comment: CRCW0603100KJNEA)
R2  value 100k  [0603]  (hidden comment: CRCW0603100KJNEA)
R3  value 10k  [0603]  (hidden comment: CRCW060310K0JNEA)
R4  value 10k  [0603]  (hidden comment: CRCW060310K0JNEA)
R6  ValueDisplayed: 0  [0603]  (hidden comment: MCR03EZPJ000)
R8  ValueDisplayed: 100k  [0603]  (hidden comment: CRCW0603100KJNEA)
R10  ValueDisplayed: 0  [0603]  (hidden comment: MCR03EZPJ000)
R11  value 100k  [0603]  (hidden comment: CRCW0603100KJNEA)
R12  ValueDisplayed: 2.7k  [0603]  (hidden comment: RC0603JR-072K7L)
R13  ValueDisplayed: 2.7k  [0603]  (hidden comment: RC0603JR-072K7L)
R14  ValueDisplayed: 2.2k  [0603]  (hidden comment: RC0603JR-072K2L)
R15  ValueDisplayed: 2.2k  [0603]  (hidden comment: RC0603JR-072K2L)
R16  ValueDisplayed: 0  [0603]  (hidden comment: MCR03EZPJ000)
R17  ValueDisplayed: 0  [0603]  (hidden comment: MCR03EZPJ000)
TP1  5009  [Keystone5009]  (value not drawn)
TP2  5009  [Keystone5009]  (value not drawn)
TP3  SCL  [Keystone5009]
TP4  SDA  [Keystone5009]
TP5  /FAULT  [Keystone5009]
TP6  MUTE  [Keystone5009]
TP7  /STANDBY  [Keystone5009]
TP12  DOUT  [Keystone5009]
U1  TPD2E007DCKR  [DCK0003A_N]
U2  TAS5411QPWPRQ1  [PWP0016B_N]
U3  6PAIC3104IRHBRQ1  [RHB0032E]  (value not drawn)

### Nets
1.8V: C16.1 C17.1 U3.32(DVDD)
3.3V: C18.1 C19.1 C20.1 C21.1 C22.1 C23.1 R1.1 R2.1 R3.1 R4.1 R8.2 R12.1 R13.1 U3.7(IOVDD) U3.18(DRVDD) U3.24(DRVDD) U3.25(AVDD)
GND: C1.2 C2.2 C3.2(-) C4.1 C11.2 C13.2 C16.2 C17.2 C18.2 C19.2 C20.2 C21.2 C22.2 C23.2 C26.2 C29.2 C30.2 J2.1 J4.1(SLEEVE) MK1.1 R11.1 U1.3(GND) U2.1(GND) U2.9(GND) U2.16(GND) U2.17(PAD) U3.6(DVSS) U3.17(AVSS1) U3.21(DRVSS) U3.26(AVSS2) U3.33(PAD)
PVDD: C1.1 C2.1 C3.1(+) U2.15(PVDD)
BCLK: U3.2(BCLK) ; off-sheet BCLK
MCLK: U3.1(MCLK) ; off-sheet MCLK
SCL: R4.2 R12.2 TP3.1 U2.5(SCL) U3.8(SCL) ; off-sheet SCL
SDA: R3.2 R13.2 TP4.1 U2.4(SDA) U3.9(SDA) ; off-sheet SDA
SDIN: U3.4(DIN) ; off-sheet SDIN
WCLK: U3.3(WCLK) ; off-sheet WCLK
NetC4_2: C4.2 J1.2 L1.2
NetC5_1: C5.1 L1.1 U2.12(OUTP)
NetC5_2: C5.2 U2.13(BSTP)
NetC6_1: C6.1 J3.2
NetC6_2: C6.2 U3.12(MIC1RP/LINE1RP)
NetC7_1: C7.1 J3.1
NetC7_2: C7.2 U3.13(MIC1RM/LINE1RM)
NetC8_1: C8.1 C9.2 R6.1
NetC8_2: C8.2 C12.2 R10.1
NetC9_1: C9.1 U2.6(IN_P)
NetC10_1: C10.1 L2.1 U2.11(OUTN)
NetC10_2: C10.2 U2.10(BSTN)
NetC11_1: C11.1 J1.1 L2.2
NetC12_1: C12.1 U2.7(IN_N)
NetC13_1: C13.1 U2.3(BYP)
NetC24_1: C24.1 J3.4
NetC24_2: C24.2 U3.10(MIC1LP/LINE1LP)
NetC25_1: C25.1 J3.3
NetC25_2: C25.2 U3.11(MIC1LM/LINE1LM)
NetC26_1: C26.1 C27.2 U3.14(MIC2L/LINE2L/MICDET)
NetC27_1: C27.1 J4.3(RING) J4.5(RING_SWITCH) R14.1 R16.2
NetC28_1: C28.1 J4.2(TIP) J4.4(TIP_SWITCH) R15.2 R17.2
NetC28_2: C28.2 C29.1 U3.16(MIC2R/LINE2R)
NetC30_1: C30.1 R14.2 R15.1 U3.15(MICBIAS)
NetJ2_2: J2.2 R8.1 U3.31(~{RESET})
NetMK1_2: MK1.2 R16.1 R17.1
NetR1_2: R1.2 TP5.1 U2.14(~{FAULT})
NetR2_2: R2.2 TP6.1 U2.8(MUTE)
NetR6_2: R6.2 U3.27(LEFT_LOP)
NetR10_2: R10.2 U3.28(LEFT_LOM)
NetR11_2: R11.2 TP7.1 U2.2(~{STANDBY})
NetTP1_1: TP1.1 U1.1(IO1) U3.30(RIGHT_LOM)
NetTP2_1: TP2.1 U1.2(IO2) U3.29(RIGHT_LOP)
NetTP12_1: TP12.1 U3.5(DOUT)

Not connected (* = marked no-connect by the designer): U3 19(HPLOUT) 20(HPLCOM) 22(HPRCOM) 23(HPROUT)

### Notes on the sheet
- To Speaker
- (near J1) -
- (near J1) +
- Choose new microphone and figure out how to bias it

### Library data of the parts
C1 C16 C19 C21 C22 = C0805C106K9PAC: CAP, CERM, 10 µF, 6.3 V, +/- 10%, X5R, 0805; Manufacturer: Kemet; Polarized: N; CompType: Capacitor; Value: 10uF; U/M: EA; Cap_F: 0.00001; Tolerance_%: 10; Value1: Unknown; VDC_V: 6.3; Value2: 6.3V; TaMin_C: -55; TaMax_C: 85; Cap_Case: 0805
C2 C13 = GRM21BR71H105KA12L: CAP, CERM, 1uF, 50V, +/-10%, X7R, 0805; Manufacturer: MuRata; Polarized: N; CompType: Capacitor; U/M: EA; Cap_F: 0.000001; Tolerance_%: 10; Value1: Unknown; VDC_V: 50; TaMin_C: -55; TaMax_C: 125; Cap_Case: 0805
C3 = EKZE500ELL331MJ25S: CAP, AL, 330 µF, 50 V, +/- 20%, 0.028 ohm, TH; Manufacturer: Chemi-Con; Polarized: Y; CompType: Capacitor; Value: 330uF; U/M: EA; Cap_F: 0.00033; Tolerance_%: 20; VDC_V: 50; Value2: 50V; ESR_ohm: 0.028; IRMS_A: 1.87; TaMin_C: -40; TaMax_C: 105; Cap_Case: 10x25mm; AEC Category: Q200; AEC Qualified: N
C4 C8 C9 C11 C12 = EMK212B7225KG-T: CAP, CERM, 2.2uF, 16V, +/-10%, X7R, 0805; Manufacturer: Taiyo Yuden; Polarized: N; CompType: Capacitor; U/M: EA; Cap_F: 0.0000022; Tolerance_%: 10; Value1: Unknown; VDC_V: 16; TaMin_C: -55; TaMax_C: 125; Cap_Case: 0805
C5 C10 = C1608X7R1H224K080AB: CAP, CERM, 0.22 µF, 50 V, +/- 10%, X7R, 0603; Manufacturer: TDK; Polarized: N; CompType: Capacitor; Value: 0.22uF; U/M: EA; Cap_F: 0.00000022; Tolerance_%: 10; Value1: Unknown; VDC_V: 50; Value2: 50V; TaMin_C: -55; TaMax_C: 125; AEC Category: Q200
C6 C7 C24 C25 C27 C28 = C2012X7R2A104K: CAP, CERM, 0.1 µF, 100 V, +/- 10%, X7R, 0805; Manufacturer: TDK; Polarized: N; CompType: Capacitor; Value: 0.1uF; U/M: EA; Cap_F: 0.0000001; Tolerance_%: 10; ESR_ohm: 0.0158; Value1: 0.0158 ohm; VDC_V: 100; Value2: 100V; TaMin_C: -55; TaMax_C: 125; Cap_Case: 0805
C17 C18 C20 C23 = C1608X7R1C104K: CAP, CERM, 0.1 µF, 16 V, +/- 10%, X7R, 0603; Manufacturer: TDK; Polarized: N; CompType: Capacitor; Value: 0.1uF; U/M: EA; Cap_F: 0.0000001; Tolerance_%: 10; ESR_ohm: 0.017; Value1: 0.017 ohm; VDC_V: 16; Value2: 16V; TaMin_C: -55; TaMax_C: 125
C26 C29 C30 = Capacitor: CAP, CERM, xxxF, xxV, [TempCo], xx%, [PackageReference]; Manufacturer: Used in BOM report; Polarized: N; U/M: EA
J1 = ED555/2DS: Terminal Block, 6A, 3.5mm Pitch, 2-Pos, TH; Manufacturer: On-Shore Technology; SymbolCreator: a0412235; CompType: Connector; U/M: EA
J2 = PBC02SAAN: as J10 on sheet TIDA-00724_TAS1020
J3 = ED555/4DS: Terminal Block, 6A, 3.5mm Pitch, 4-Pos, TH; Manufacturer: On-Shore Technology; SymbolCreator: a0412235; CompType: Connector; U/M: EA
J4 = SJ1-3515-SMT-TR-PI: Audio Jack, 3.5mm, Stereo, R/A, Pink, SMT; Manufacturer: CUI Inc.; SymbolCreator: a0412235; U/M: EA
L1 L2 = DFEG7030D-150M: Inductor, Shielded, Metal Composite, 15 µH, 2.7 A, 0.179 ohm, AEC-Q200 Grade 1, SMD; Manufacturer: Toko; Value: 15uH; Ind_H: 15.0E-6; Imax_A: 2.7; Irms: 2.7A @ 40C rise; Isat: 3.2A @ 20% inductance drop; DCR_ohm: 0.179; Value2: 2.7A; AEC Category: Q200; AEC Qualified: Y; AEC Grade: 1
MK1 = CMA-4544PF-W: Microphone, Electret Condenser, Omnidirectional, -44 dB, TH; Manufacturer: CUI Inc.; SymbolCreator: a0412235
R1 R2 R11 = CRCW0603100KJNEA: RES, 100k ohm, 5%, 0.1W, 0603; Manufacturer: Vishay-Dale; CompType: Resistor; Res_ohm: 100000; Tolerance_%: 5; Power_W: 0.1; VDC_V: 75; TempCo: 200 ppm/C; EIA_Code: E24; U/M: EA
R3 R4 = CRCW060310K0JNEA: RES, 10k ohm, 5%, 0.1W, 0603; Manufacturer: Vishay-Dale; CompType: Resistor; Res_ohm: 10000; Value_Code: 10k0; Tolerance_%: 5; Power_W: 0.1; VDC_V: 75; TempCo: 200 ppm/C; EIA_Code: E24; U/M: EA
R6 R10 R16 R17 = MCR03EZPJ000: RES, 0, 5%, 0.1 W, 0603; Manufacturer: Rohm; CompType: Resistor; Value: 0; Value_Code: 0000; Tolerance_%: 5; Power_W: 0.1; Value2: 0.1W; VDC_V: 50; TempCo: 400 ppm/C; EIA_Code: E24; U/M: EA
R8 = CRCW0603100KJNEA: RES, 100 k, 5%, 0.1 W, 0603; Manufacturer: Vishay-Dale; CompType: Resistor; Value: 100k; Res_ohm: 100000; Tolerance_%: 5; Power_W: 0.1; Value2: 0.1W; VDC_V: 75; TempCo: 200 ppm/C; EIA_Code: E24; U/M: EA
R12 R13 = RC0603JR-072K7L: RES, 2.7 k, 5%, 0.1 W, 0603; Manufacturer: Yageo America; CompType: Resistor; Value: 2.7k; Res_ohm: 2700; Value_Code: 2k70; Tolerance_%: 5; Power_W: 0.1; Value2: 0.1W; VDC_V: 50; TempCo: 100 ppm/C; EIA_Code: E24; U/M: EA
R14 R15 = RC0603JR-072K2L: RES, 2.2 k, 5%, 0.1 W, 0603; Manufacturer: Yageo America; CompType: Resistor; Value: 2.2k; Res_ohm: 2200; Value_Code: 2k20; Tolerance_%: 5; Power_W: 0.1; Value2: 0.1W; VDC_V: 50; TempCo: 100 ppm/C; EIA_Code: E24; U/M: EA
TP1-TP7 TP12 = 5009: as TP8 on sheet TIDA-00724_Power
U1 = TPD2E007DCKR: ESD Protection Array for AC Signal Data Interface, 2 Channels, -40 to +85 degC, 3-pin SC70 (DCK), Green (RoHS & no Sb/Br); Manufacturer: Texas Instruments; Alternate PartNumber: Equivalent; Breakdown Voltage(Min)(V): +/-14; IEC 61000-4-2 Air-Gap(+/- kV): 15; IEC 61000-4-2 Contact(+/- kV): 8; IO Leakage Current(nA): 50; SubFamily: ESD Solution
U2 = TAS5411QPWPRQ1: 8-W Mono Automotive Digital-Audio Amplifier With Load Dump and I2C Diagnostics, PWP0016B; Manufacturer: Texas Instruments; SymbolCreator: a0411947; CompType: IC; U/M: EA
U3 = 6PAIC3104IRHBRQ1: LOW-POWER STEREO AUDIO CODEC, RHB0032E; Manufacturer: Texas Instruments; SymbolCreator: Altium; CompType: IC; U/M: EA

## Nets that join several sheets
1.8V: TIDA-00724_Power (C36.1 TP10.1 U5.5), TIDA-00724_Audio (C16.1 C17.1 U3.32)
3.3V: TIDA-00724_Power (5 pins), TIDA-00724_TAS1020 (K1.4 R24.2 R25.2), TIDA-00724_Audio (17 pins)
GND: TIDA-00724_Power (15 pins), TIDA-00724_TAS1020 (41 pins), TIDA-00724_Audio (31 pins)
PVDD: TIDA-00724_Power (5 pins), TIDA-00724_Audio (C1.1 C2.1 C3.1 U2.15)
BCLK: TIDA-00724_TAS1020 (J11.1 R36.1), TIDA-00724_Audio (U3.2)
MCLK: TIDA-00724_TAS1020 (J10.1 R29.1), TIDA-00724_Audio (U3.1)
SCL: TIDA-00724_TAS1020 (J8.1 R24.1 U6.6 U9.44), TIDA-00724_Audio (5 pins)
SDA: TIDA-00724_TAS1020 (J8.3 R25.1 U6.5 U9.43), TIDA-00724_Audio (5 pins)
SDIN: TIDA-00724_TAS1020 (J13.1 R41.1), TIDA-00724_Audio (U3.4)
WCLK: TIDA-00724_TAS1020 (J12.1 R39.1), TIDA-00724_Audio (U3.3)

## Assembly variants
001: not fitted C8 C26 C29 C30 C54 C55 FID1 FID2 FID3 R60 R62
